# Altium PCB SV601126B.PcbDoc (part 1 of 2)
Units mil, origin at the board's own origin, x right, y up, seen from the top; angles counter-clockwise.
Board outline 2770 x 1865 mil, 4 copper layers (Top Layer, MidLayer1, MidLayer2, Bottom Layer), stack 61.2 mil thick; 102 components, 62 nets, 339 pads, 118 vias.
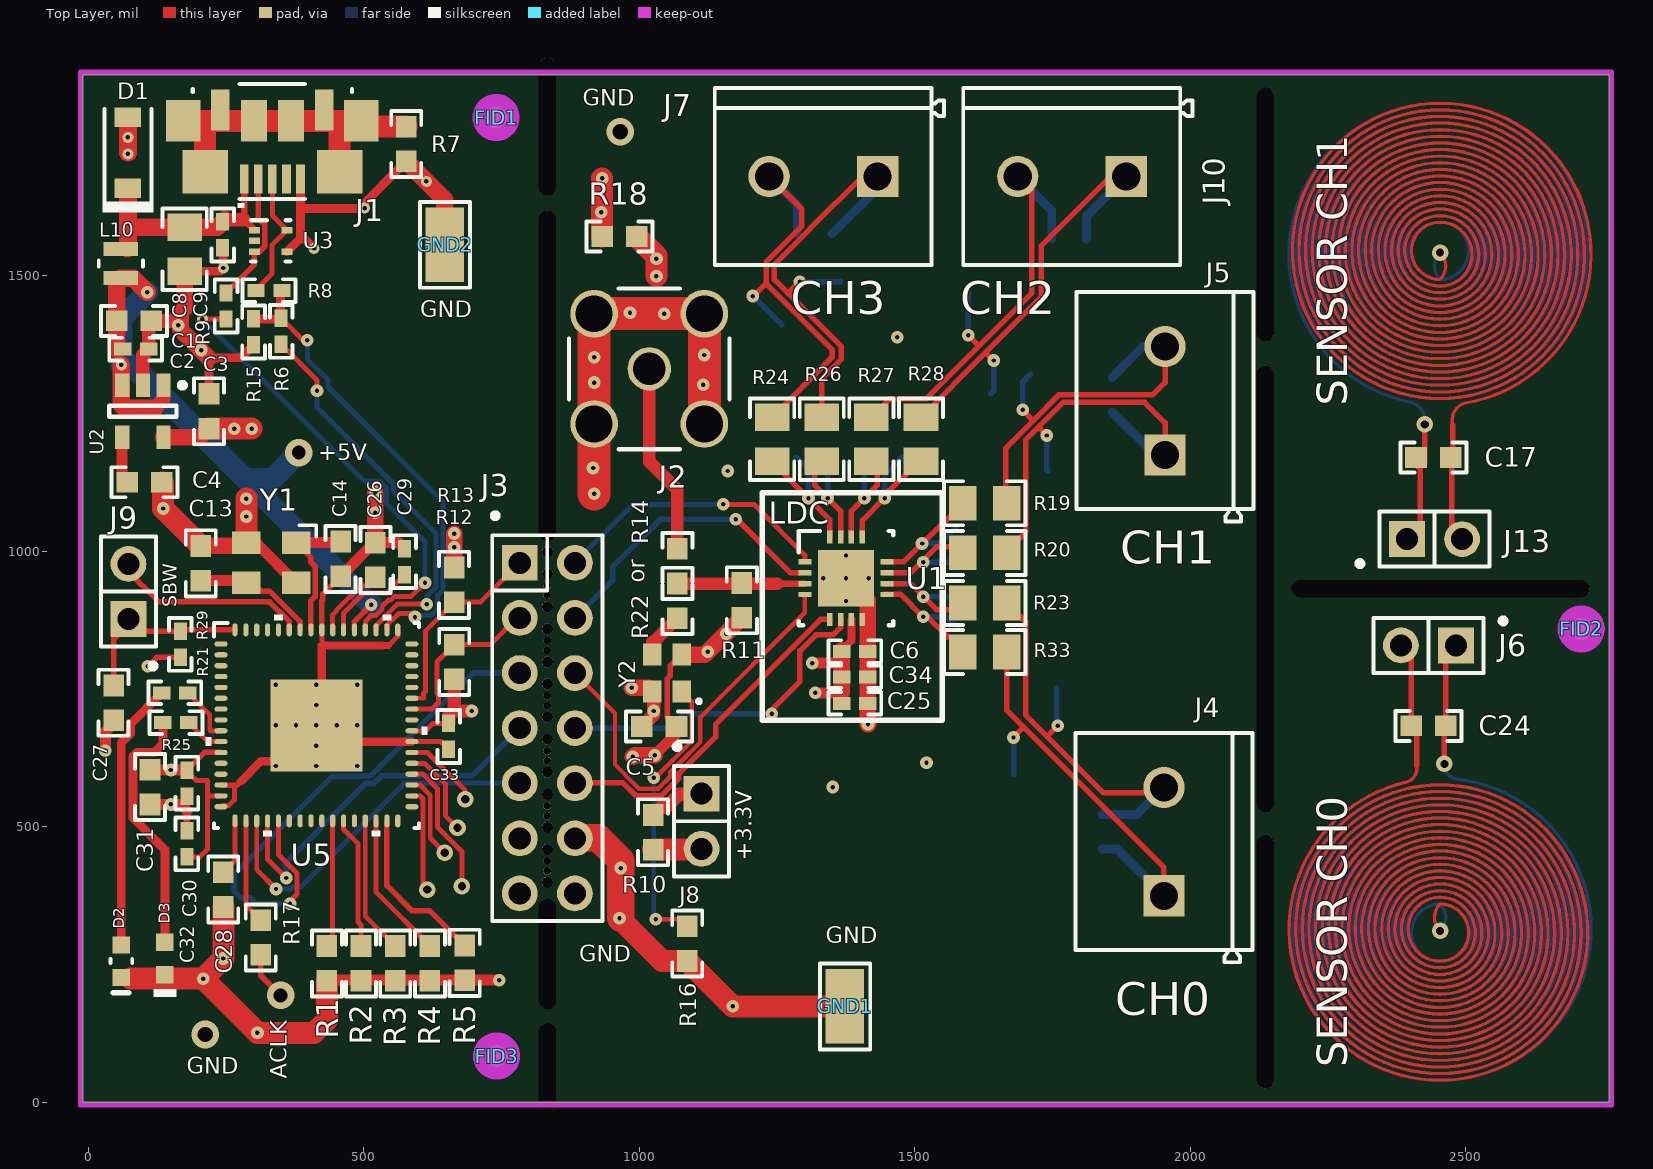
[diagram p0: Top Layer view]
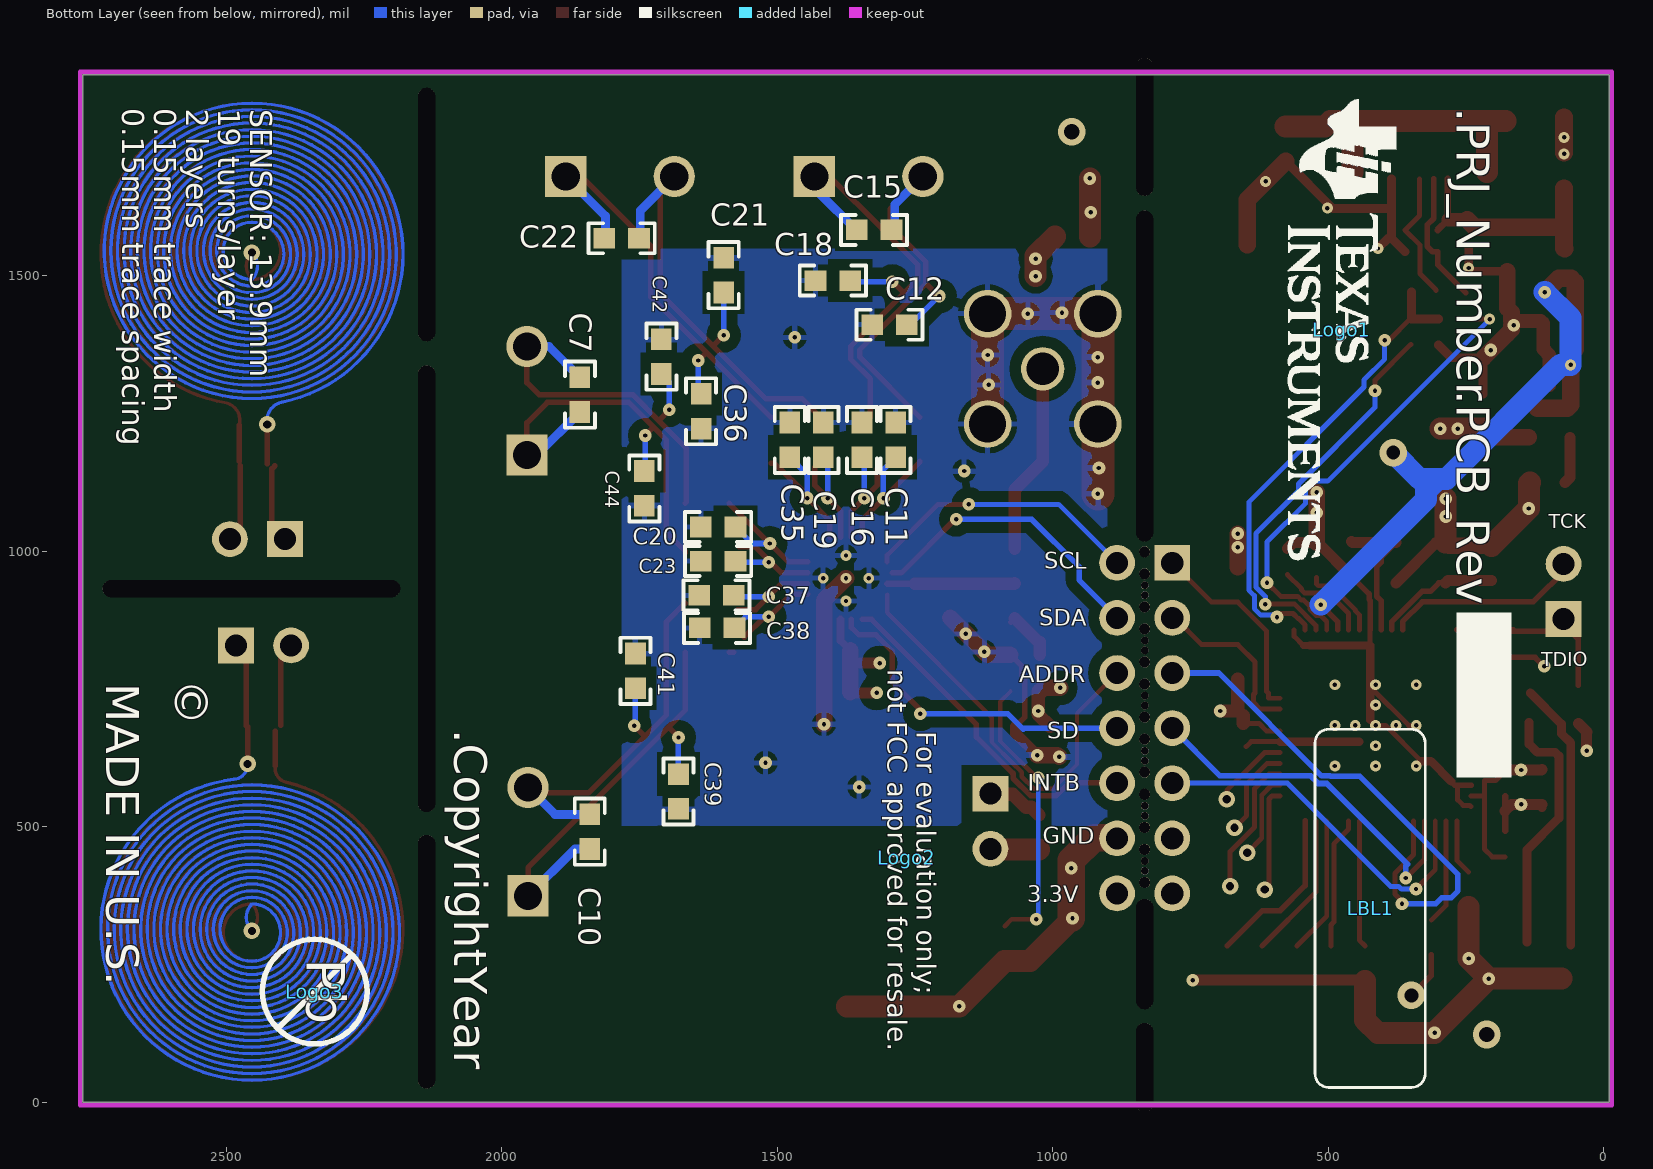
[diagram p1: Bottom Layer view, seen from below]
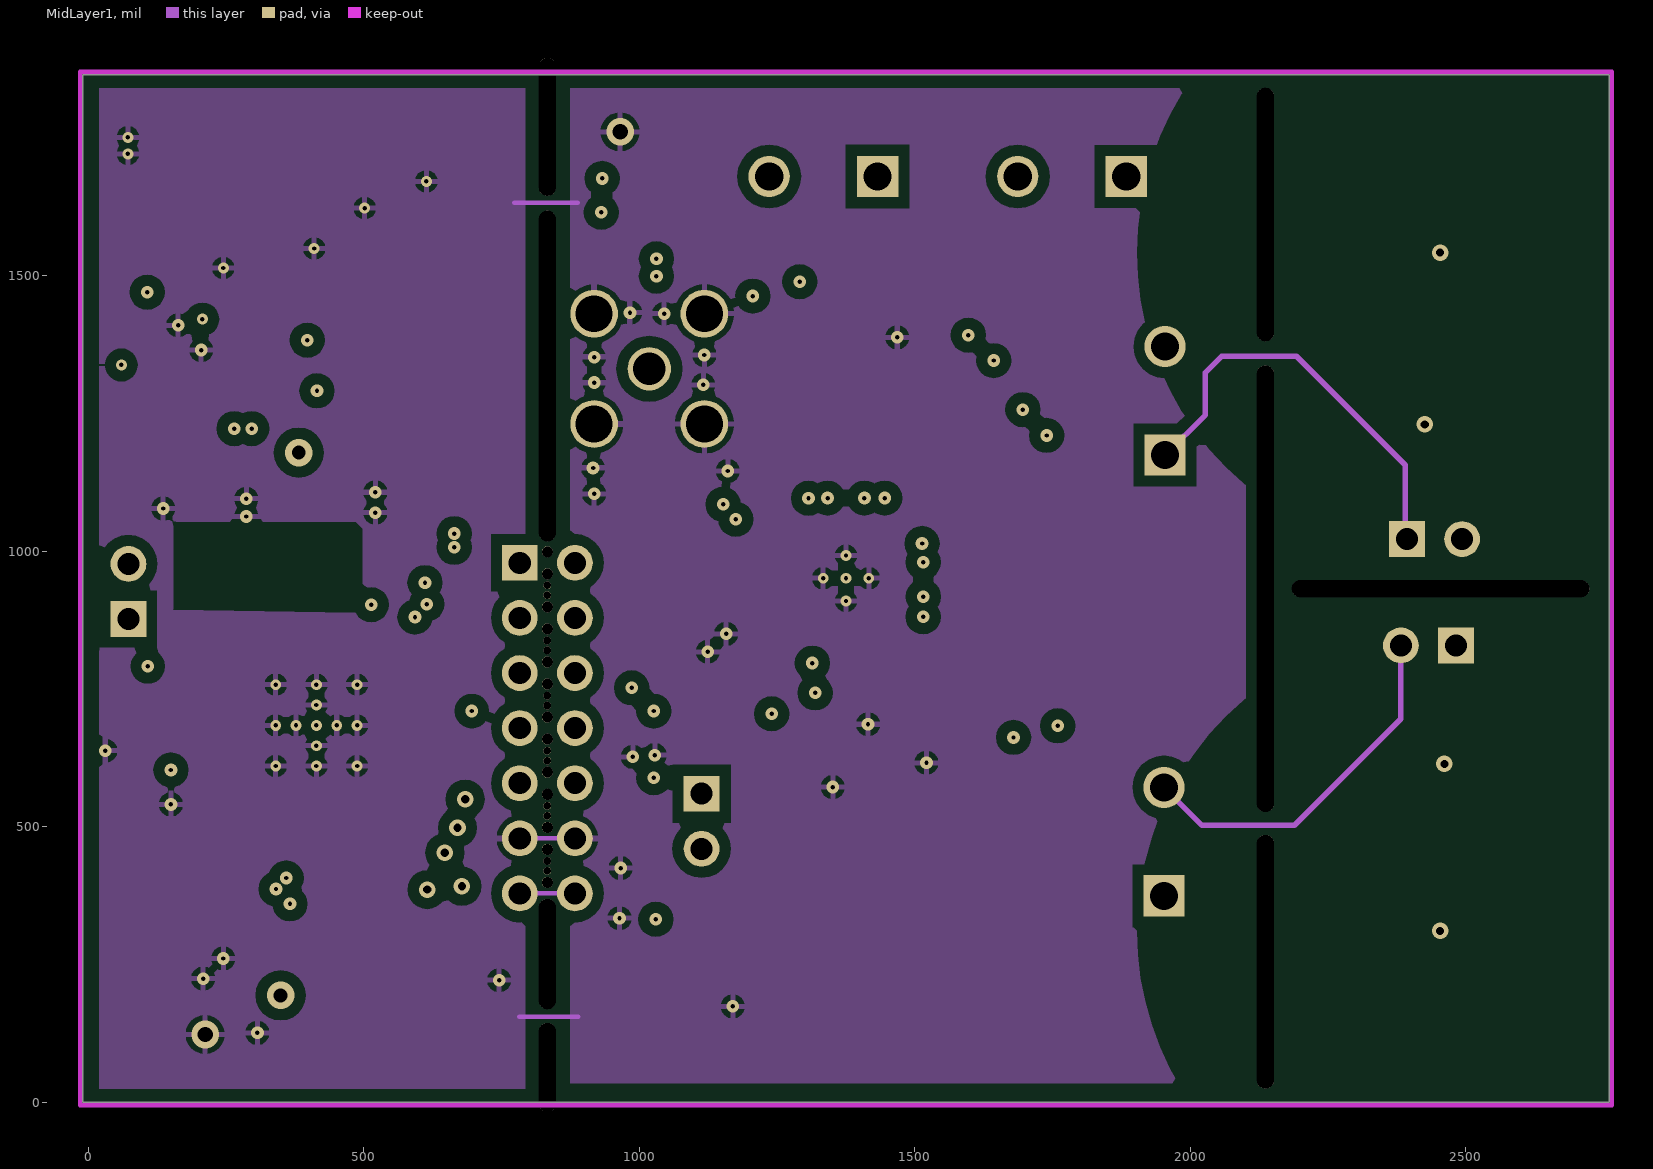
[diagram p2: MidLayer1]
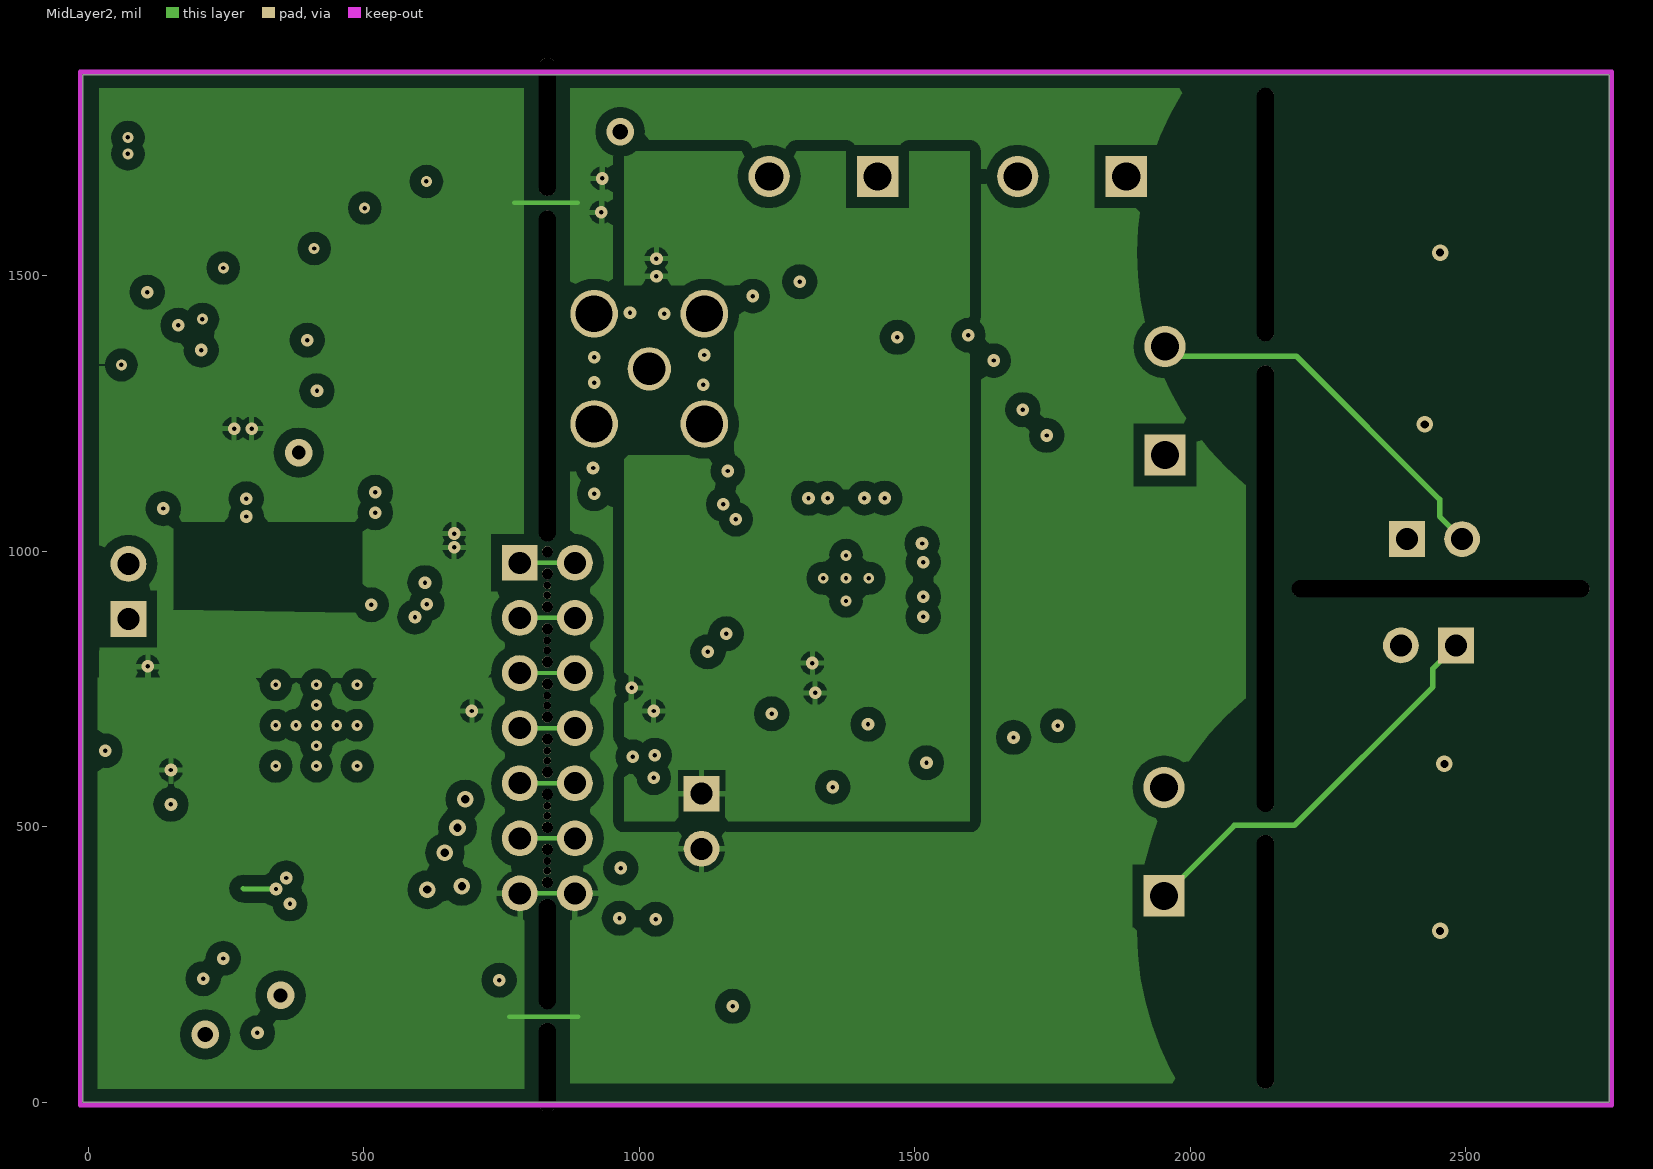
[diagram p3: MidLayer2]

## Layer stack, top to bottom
Top Solder: solder mask 0.4, Solder Resist, Dk 3.5
Top Layer: signal copper 1.4
Dielectric1: core 12.6, FR-4, Dk 3.9
MidLayer1: signal copper 1.4
Dielectric2: prepreg 30.4, FR-4, Dk 3.9
MidLayer2: signal copper 1.4
Dielectric3: core 12.6, FR-4, Dk 4.8
Bottom Layer: signal copper 1.4
Bottom Solder: solder mask 0.4, Solder Resist, Dk 3.5

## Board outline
-10,0 2760,0 2760,1865 -10,1865

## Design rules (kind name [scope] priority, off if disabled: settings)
AcuteAngle [All] p1: minimum=4.50000000000000E+0001 checktracksonly=FALSE
AssemblyTestPointUsage [All] p1: valid=2
Clearance Clearance_BoardEdge_MountingHoles [OnCopper and InComponentClass('Mounting Holes') vs IsKeepOut] p1: gap=40
Clearance Clearance_BoardEdge_Poly [OnCopper and InPoly vs IsKeepOut] p2: gap=25
Clearance Clearance_BoardEdge [OnCopper and Not InComponentClass('Logo') and not InComponentClass('FiducialMark') and not InRegion(1000,500,4000,800) and Not IsKeepout vs IsKeepOut] p3: gap=30
Clearance Clearance_Poly [InPolygon] p4: gap=20
Clearance [All] p5: gap=4
ComponentClearance ComponentClearance_Logo [InComponentClass('Logo')] p1: gap=50 collisioncheckmode=3 verticalgap=10 showdistances=FALSE
ComponentClearance ComponentClearance_ScrewToNut [(HasFootprint('NY PMS 440 0025 PH')) vs (HasFootprint('Keystone_1902C'))] p2: gap=5 collisioncheckmode=3 verticalgap=10 showdistances=FALSE
ComponentClearance ComponentClearance_MountingHoles [InComponentClass('Mounting Holes')] p3: gap=250 collisioncheckmode=3 verticalgap=100000 showdistances=FALSE
ComponentClearance ComponentClearance_SmallPassives [HasFootprint('0201*') or HasFootprint('0402*') or HasFootprint('0508') or HasFootprint('0603*') or HasFootprint('0612') or HasFootprint('0805*') or HasFootprint('0815*') or HasFootprint('0830*') or HasFootprint('1206*') or HasFootprint('1210*') or HasFootprint('1808*') or HasFootprint('1812*') or HasFootprint('1825*') or HasFootprint('2010*') or HasFootprint('2220*') or HasFootprint('2225*') or HasFootprint('2512*') or HasFootprint('2728*') or HasFootprint('3518*') vs HasFootprint('0201*') or HasFootprint('0402*') or HasFootprint('0508') or HasFootprint('0603*') or HasFootprint('0612') or HasFootprint('0805*') or HasFootprint('0815*') or HasFootprint('0830*') or HasFootprint('1206*') or HasFootprint('1210*') or HasFootprint('1808*') or HasFootprint('1812*') or HasFootprint('1825*') or HasFootprint('2010*') or HasFootprint('2220*') or HasFootprint('2225*') or HasFootprint('2512*') or HasFootprint('2728*') or HasFootprint('3518*')] p4: gap=20 collisioncheckmode=3 verticalgap=10 showdistances=FALSE
ComponentClearance ComponentClearance_THtoSMT [IsThruComponent vs IsSMTComponent] p5: gap=75 collisioncheckmode=3 verticalgap=30 showdistances=FALSE
ComponentClearance ComponentClearance_THtoTH [IsThruComponent vs IsThruComponent] p6: gap=78.74 collisioncheckmode=3 verticalgap=30 showdistances=TRUE
ComponentClearance [All] p7: gap=40 collisioncheckmode=3 verticalgap=10 showdistances=FALSE
DiffPairsRouting [All] p1: maxlimit=100 minlimit=10 mostfreqgap=10 toplayer_minwidth=15 toplayer_maxwidth=15 toplayer_prefwidth=15 midlayer1_minwidth=15 midlayer1_maxwidth=15 midlayer1_prefwidth=15 midlayer2_minwidth=15 midlayer2_maxwidth=15 midlayer2_prefwidth=15 bottomlayer_minwidth=15 bottomlayer_maxwidth=15 bottomlayer_prefwidth=15 maxuncoupledlength=1000
FabricationTestPointUsage TestPointUsage [All] p1: valid=2 allowmultiple=FALSE
FabricationTestpoint Testpoint [All] p1: side=3 testpointundercomponent=TRUE minsize=40 maxsize=100 preferedsize=60 minholesize=0 maxholesize=40 preferedholesize=32 testpointgrid=1 allowsidetop=TRUE allowsidebottom=TRUE usegrid=TRUE gridtolerance=0.01
FanoutControl Fanout_LCC [IsLCC] p1: bgadir=Out bgaviamode=Centered fanoutstyle=Auto fanoutdirection=Alternating viagrid=1 // Fanout_LCC (Default Rule)
FanoutControl Fanout_BGA [IsBGA] p2: bgadir=Out bgaviamode=Centered fanoutstyle=Auto fanoutdirection=Alternating viagrid=1 // Fanout_BGA (Default Rule)
FanoutControl Fanout_Default [All] p4: bgadir=Out bgaviamode=Centered fanoutstyle=Auto fanoutdirection=Alternating viagrid=1 // Fanout_Default (Default Rule)
FanoutControl Fanout_Small [(CompPinCount < 5)] p5: bgadir=Out bgaviamode=Centered fanoutstyle=Auto fanoutdirection=OutThenIn viagrid=1 // Fanout_Small (Default Rule)
HoleSize [All] p1: absolutevalues=TRUE maxlimit=251 minlimit=7.87 maxpercent=80.000 minpercent=20.000
HoleToHoleClearance [All] p1: gap=21 allowstackedmicrovias=TRUE
MinimumAnnularRing MinimumAnnularRing_ThermalPadVias [IsVia and InAnyComponent] p1: minimumring=5.91
MinimumAnnularRing [All] p2: minimumring=6
MinimumSolderMaskSliver MinimumSolderMaskSliver_Logo [InComponentClass('Logo') vs InComponentClass('Logo')] p1: minsoldermaskwidth=0.7
MinimumSolderMaskSliver [All] p2: minsoldermaskwidth=3.94
PlaneConnect [All] p1: planeconnectstyle=Relief reliefexpansion=10 reliefentries=4 reliefconductorwidth=10 reliefairgap=10
PolygonConnect [All] p1: connectstyle=Relief reliefconductorwidth=10 reliefentries=4 polygonreliefangle="90 Angle" airgapwidth=10
RoutingVias ThermalPadVias [IsVia and InAnyComponent] p1: holewidth=7.87 width=19.68 viastyle="Through Hole" minholewidth=7.87 minwidth=19.68 maxholewidth=12.99 maxwidth=23.62
RoutingVias [All] p2: holewidth=16 width=34 viastyle="Through Hole" minholewidth=7.87 minwidth=20 maxholewidth=40 maxwidth=65
SMDToCorner [All] p1: distance=30000
SilkToSilkClearance [All] p1: silktosilkclearance=5
SilkToSolderMaskClearance SilkscreenOverComponentPads [IsPad] p1: minsilkscreentomaskgap=5 clearancetoexposedcopper=TRUE
SolderMaskExpansion [All] p1: expansion=1.97
UnpouredPolygon [All] p1: allowunpoured=FALSE
Width [All] p1: maxlimit=100 minlimit=4 preferedwidth=10 checkconnectedcopper=TRUE
14 further rules are at their usual default settings.

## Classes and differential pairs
component class Label: LBL1
component class FiducialMark: FID1 FID2 FID3
component class Logo: Logo1
component class Header: J3 J6 J8 J9 J13

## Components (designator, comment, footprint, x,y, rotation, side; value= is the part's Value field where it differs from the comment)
C1 "C1608X5R1A106M" 0603 83,1418 r0 top
C2 "GRM155R71C104JA88D" 0402 85.99,1366.82 r0 top
C3 "C0603C225K8PACTU" 0603 219,1254 r90 top
C4 "C1608C0G1E103J" 0603 102,1125 r0 top
C5 "C1608C0G1E103J" 0603 1036,682 r0 top
C6 "C1005X7R1C103K" 0402 1391,818 r0 top
C7 "C1608C0G1H331F080AA" 0603 1858,1284 r270 bottom
C8 "C2012X5R1C226K125AC" 0805_HV 175,1548 r270 top
C9 "GRM155R71C104JA88D" 0402 244,1574 r270 top
C10 "C1608C0G1H331F080AA" 0603 1840,491 r270 bottom
C11 "GRM1885C2A180JA01D" 0603 1285,1202 r270 bottom
C12 "GRM1885C2A180JA01D" 0603 1296,1411 r180 bottom
C13 "GRM1885C2A180JA01D" 0603 204,978 r270 top
C14 "GRM1885C2A180JA01D" 0603 458,986 r90 top
C15 "C1608C0G1H331F080AA" 0603 1324,1583 r0 bottom
C16 "GRM1885C2A180JA01D" 0603 1346,1202 r90 bottom
C17 "C1608C0G1H331F080AA" 0603 2441,1170 r0 top
C18 "GRM1885C2A180JA01D" 0603 1399,1491 r0 bottom
C19 "GRM1885C2A180JA01D" 0603 1416,1202 r270 bottom
C20 "GRM1885C2A180JA01D" 0603 1607,1044 r180 bottom
C21 "GRM1885C2A180JA01D" 0603 1597,1501 r270 bottom
C22 "C1608C0G1H331F080AA" 0603 1782,1568 r0 bottom
C23 "GRM1885C2A180JA01D" 0603 1607,982 r0 bottom
C24 "C1608C0G1H331F080AA" 0603 2432,683 r0 top
C25 "GRM155R61A105KE15D" 0402 1391,724 r0 top
C26 "06035A221FAT2A" 0603 521,984 r270 top
C27 "C0603X222K5RACTU" 0603 46,725 r90 top
C28 "C0603C474K8RACTU" 0603 245,386 r270 top
C29 "C1005C0G1H221F050BA" 0402 574,981 r90 top
C30 "GRM155R71C104JA88D" 0402 179,579 r270 top
C31 "C1608X5R1A106M" 0603 112,572 r270 top
C32 "GRM155R71C104JA88D" 0402 179,469 r90 top
C33 "GRM155R71C104JA88D" 0402 654,664 r270 top
C34 "GRM155R71C104JA88D" 0402 1391,772 r0 top
C35 "GRM1885C2A180JA01D" 0603 1477,1202 r90 bottom
C36 "GRM1885C2A180JA01D" 0603 1638,1254 r270 bottom
C37 "GRM1885C2A180JA01D" 0603 1610,920 r180 bottom
C38 "GRM1885C2A180JA01D" 0603 1609,861 r0 bottom
C39 "GRM1885C2A180JA01D" 0603 1679,564 r90 bottom
C41 "GRM1885C2A180JA01D" 0603 1757,783 r90 bottom
C42 "GRM1885C2A180JA01D" 0603 1710,1353 r270 bottom
C44 "GRM1885C2A180JA01D" 0603 1741,1114 r270 bottom
D1 "MMSZ5232B-7-F" SOD-123 72,1723 r90 top
D2 "LG L29K-G2J1-24-Z" "LG L29K_GREEN" 60,256 r270 top
D3 "SML-LX0603SRW-TR" SML-LX0603SRW_SuperRed 139,261 r270 top
FID1 "Fiducial" Fiducial10-20 740,1787 r0 top
FID2 "Fiducial" Fiducial10-20 2709,859 r0 top
FID3 "Fiducial" Fiducial10-20 741,84 r0 top
GND1 "5015" Testpoint_Keystone_Miniature 1373,174 r90 top
GND2 "5015" Testpoint_Keystone_Miniature 647,1556 r90 top
J1 "ZX62R-B-5P" Hirose_ZX62R-B-5P 334,1781 r90 top
J2 "901-144-8RFX" Amphenol_901-144-8RFX 1018,1331 r90 top
J3 "TSW-107-07-G-D" TSW-107-07-G-D 833,679 r270 top
J4 "1729018" Phoenix_1729018 1952,473 r90 top
J5 "1729018" Phoenix_1729018 1954,1273 r90 top
J6 "TSW-102-07-G-S" TSW-102-07-G-S 2432,829 r180 top
J7 "1729018" Phoenix_1729018 1334,1680 r180 top
J8 "TSW-102-07-G-S" TSW-102-07-G-S 1113,510 r270 top
J9 "TSW-102-07-G-S" TSW-102-07-G-S 73,927 r90 top
J10 "1729018" Phoenix_1729018 1785,1680 r180 top
J13 "TSW-102-07-G-S" TSW-102-07-G-S 2443,1022 r0 top
L10 "VLS201610ET-100M" VLS201610ET 59,1522 r270 top
LBL1 "Size: 0.65\" x 0.20 \"" Label_650x200 424,352 r90 bottom
Logo1 "Texas Instruments" TI_Stacked_Overlay_Small 475,1402 r270 bottom
Logo2 "FCC disclaimer" FCC_disclaimer_stacked 1265,444 r270 bottom
Logo3 "Pb-Free Symbol" Pb-Free_Overlay_Medium 2339,201 r270 bottom
R1 "CRCW06030000Z0EA" 0603 433,252 r270 top
R2 "CRCW06030000Z0EA" 0603 495,252 r270 top
R3 "CRCW06030000Z0EA" 0603 557,252 r270 top
R4 "CRCW06030000Z0EA" 0603 620,252 r270 top
R5 "CRCW06030000Z0EA" 0603 683,253 r270 top
R6 "CRCW04021K50JNED" 0402 350,1399 r270 top
R7 "CRCW060333R0JNEA" 0603 577,1739 r90 top
R8 "CRCW040210R0FKED" 0402 328,1473 r0 top
R9 "CRCW040210R0FKED" 0402 250,1445 r270 top
R10 "CRCW06030000Z0EA" 0603 1025,490 r90 top
R11 "CRCW060350R0FKEA" 0603 1186,911 r90 top
R12 "RC0603FR-074K7L" 0603 664,799 r270 top
R13 "RC0603FR-074K7L" 0603 664,939 r90 top
R14 "CRCW060333R0JNEA" 0603 1069,973 r90 top
R15 "RC0402JR-071ML" 0402 300,1398 r90 top
R16 "CRCW06030000Z0EA" 0603 1087,288 r90 top
R17 "CRCW060333R0JNEA" 0603 313,299 r270 top
R18 "CRCW06030000Z0EA" 0603 964,1571 r0 top
R19 "CRCW08050000Z0EA" 0805_HV 1627,1087 r0 top
R20 "CRCW08050000Z0EA" 0805_HV 1627,997 r0 top
R21 "CRCW04021K00JNED" 0402 157,743 r180 top
R22 "CRCW06030000Z0EA" 0603 1069,910 r90 top
R23 "CRCW08050000Z0EA" 0805_HV 1627,906 r0 top
R24 "CRCW08050000Z0EA" 0805_HV 1241,1203 r90 top
R25 "CRCW04021K00JNED" 0402 159,689 r180 top
R26 "CRCW08050000Z0EA" 0805_HV 1331,1203 r90 top
R27 "CRCW08050000Z0EA" 0805_HV 1421,1203 r90 top
R28 "CRCW08050000Z0EA" 0805_HV 1511,1203 r90 top
R29 "CRCW040233K0JNED" 0402 167,831 r90 top
R33 "CRCW08050000Z0EA" 0805_HV 1627,817 r0 top
U1 "LDC1314RGH" RGH0016A 1375,951 r0 top
U2 "LP2985AIM5-3.3/NOPB" MF05A_N 99,1254 r270 top
U3 "TPD2E001DRLR" DRL0005A 331,1563 r0 top
U5 "MSP430F5528IRGC" RGC0064B 414,684 r0 top
Y1 "ABM8-24.000MHZ-B2-T" XTAL_ABM8 332,979 r270 top
Y2 "625L3C040M00000" OSC_CTS_625 1050,779 r180 top

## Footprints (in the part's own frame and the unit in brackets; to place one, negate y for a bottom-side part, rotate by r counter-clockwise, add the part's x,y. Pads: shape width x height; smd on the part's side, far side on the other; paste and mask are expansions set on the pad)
0402 [mm] "0402 from SM-752 data"
  rect 0.8x0.6 smd: 1(-0.6,0) 2(0.6,0)
  silkscreen extent -1.22,-0.52 1.22,0.52, body extent -0.55,-0.3 0.55,0.3, height 0.6
0603 [mm] "0603 from SM-752 data"
  rect 1x0.95 smd: 1(-0.8,0) 2(0.8,0)
  silkscreen extent -1.52,-0.69 1.52,0.69, body extent -0.87,-0.47 0.87,0.47, height 0.85
0805_HV [mil] "0805 with 30mil clearance between pads"
  rect 50x63 smd: 1(-40,0) 2(40,0)
  silkscreen extent -74,-40 74,40, body extent -43,-29 43,29, height 43
Amphenol_901-144-8RFX [mm] "SMA Straight Jack, TH"
  round 2 hole 1.5: 1(0,0)
  round 2.2 hole 1.7: 2(-2.54,2.54) 3(-2.54,-2.54) 4(2.54,-2.54) 5(2.54,2.54)
  silkscreen extent -3.7,-3.7 3.7,3.7, body extent -3.7,-3.7 3.7,3.7, height 9.93
DRL0005A [mm] "SOTFL, 5-Flat Leads, Body 1.2x1.6x0.6mm, Pitch 0.5mm, TI recommended"
  rect 0.5x0.3 smd: 1(-0.75,0.5) 2(-0.75,0) 3(-0.75,-0.5) 4(0.75,-0.5) 5(0.75,0.5)
  silkscreen extent -0.9,-0.95 0.9,0.95, body extent -0.85,-0.85 0.85,0.85, height 0.62
FCC_disclaimer_stacked [mil]
Fiducial10-20 [mm]
  round 1 smd mask+0.5: 1(0,0)
  Top Layer keep-out circle w1.178: c0,0 r0.5
Hirose_ZX62R-B-5P [mm] "Hirose"
  rect 1.35x0.4 smd: 1(-2.68,1.3) 2(-2.68,0.65) 3(-2.68,0) 4(-2.68,-0.65) 5(-2.68,-1.3)
  rect 2x2.1 smd: 6(-2.35,-3.1) 7(-2.35,3.1)
  rect 1.9x1.6 smd: 8(0,-4.1) 13(0,4.1)
  rect 1.88x0.85 smd: 9(0.495,-2.4) 12(0.495,2.4)
  rect 1.9x1.2 smd: 10(0,-0.85) 11(0,0.85)
  silkscreen extent -4,-3.67 1.7,3.67, body extent -2.57,-3.48 2.11,3.45, height 2.65
Label_650x200 [mil] "Thermal Transfer Label"
  round 1 on Mech14: 0(0,0)
  silkscreen extent -325,-100 325,100, body extent -326,-101 326,101, height 1
"LG L29K_GREEN" [mm] "OSRAM"
  rect 0.8x0.8 smd paste-0.4: 1(-0.75,0) 2(0.75,0)
  silkscreen extent -0.1,-0.5 1.45,0.5, body extent -0.9,-0.45 0.9,0.45, height 0.67
MF05A_N [mm] "SOT23, 5-Leads, Body 2.9x1.6mm, Pitch 0.95mm, Lead Span 2.8mm, IPC Medium Density"
  rect 1.1x0.65 smd: 1(-1.2,0.95) 2(-1.2,0) 3(-1.2,-0.95) 4(1.2,-0.95) 5(1.2,0.95)
  silkscreen extent -1.32,-1.55 0.25,1.95, body extent -0.9,-1.55 0.9,1.55, height 1.19
OSC_CTS_625 [mm] "CTS"
  rect 0.85x1 smd: 1(-0.675,0.85) 2(-0.675,-0.85) 3(0.675,-0.85) 4(0.675,0.85)
  silkscreen extent -1.53,1.25 -1.43,1.35, body extent -1.1,-1.35 1.1,1.35, height 1.02
Pb-Free_Overlay_Medium [mil]
  silkscreen extent -95,-95 95,95
Phoenix_1729018 [mm] "Phoenix Contact"
  rect 1.905x1.905 hole 1.3: 1(-2.5,0)
  round 1.9 hole 1.3: 2(2.5,0)
  silkscreen extent -5.56,-4.08 5.01,4.07, body extent -5.56,-4.08 5.01,4.07, height 10
RGC0064B [mm]
  oval 0.6x0.24 smd mask+0.07: 1(-4.4,3.75) 2(-4.4,3.25) 3(-4.4,2.75) 4(-4.4,2.25) 5(-4.4,1.75) 6(-4.4,1.25) 7(-4.4,0.75) 8(-4.4,0.25) 9(-4.4,-0.25) 10(-4.4,-0.75) 11(-4.4,-1.25) 12(-4.4,-1.75) 13(-4.4,-2.25) 14(-4.4,-2.75) 15(-4.4,-3.25) 16(-4.4,-3.75) 33(4.4,-3.75) 34(4.4,-3.25) 35(4.4,-2.75) 36(4.4,-2.25) 37(4.4,-1.75) 38(4.4,-1.25) 39(4.4,-0.75) 40(4.4,-0.25) 41(4.4,0.25) 42(4.4,0.75) 43(4.4,1.25) 44(4.4,1.75) 45(4.4,2.25) 46(4.4,2.75) 47(4.4,3.25) 48(4.4,3.75)
  oval 0.24x0.6 smd mask+0.07: 17(-3.751,-4.4) 18(-3.251,-4.4) 19(-2.751,-4.4) 20(-2.251,-4.4) 21(-1.75,-4.4) 22(-1.25,-4.4) 23(-0.75,-4.4) 24(-0.25,-4.4) 25(0.25,-4.4) 26(0.75,-4.4) 27(1.25,-4.4) 28(1.75,-4.4) 29(2.251,-4.4) 30(2.751,-4.4) 31(3.251,-4.4) 32(3.751,-4.4) 49(3.751,4.4) 50(3.251,4.4) 51(2.751,4.4) 52(2.251,4.4) 53(1.75,4.4) 54(1.25,4.4) 55(0.75,4.4) 56(0.25,4.4) 57(-0.25,4.4) 58(-0.75,4.4) 59(-1.25,4.4) 60(-1.75,4.4) 61(-2.251,4.4) 62(-2.751,4.4) 63(-3.251,4.4) 64(-3.751,4.4)
  rect 4.25x4.25 smd paste-2.112: 65(0,0)
  silkscreen extent -5.1,-5.1 5.1,5.1, body extent -4.57,-4.57 4.57,4.57, height 1.01
RGH0016A [mm] "QFN, 16-Leads, Body 4x4mm, Pitch 0.5mm, TI Recommended"
  rect 0.6x0.25 smd: 1(-1.9,0.75) 2(-1.9,0.25) 3(-1.9,-0.25) 4(-1.9,-0.75) 9(1.9,-0.75) 10(1.9,-0.25) 11(1.9,0.25) 12(1.9,0.75)
  rect 0.25x0.6 smd: 5(-0.75,-1.9) 6(-0.25,-1.9) 7(0.25,-1.9) 8(0.75,-1.9) 13(0.75,1.9) 14(0.25,1.9) 15(-0.25,1.9) 16(-0.75,1.9)
  rect 2.6x2.6 smd paste-1.3: 17(0,0)
  silkscreen extent -2.17,-2.17 2.17,2.17, body extent -2.05,-2.05 2.05,2.05, height 0.81
SML-LX0603SRW_SuperRed [mm] "Lumex Opto/Components Inc"
  rect 0.8x0.8 smd: 1(-0.75,0) 2(0.75,0)
  silkscreen extent 1.4,-0.53 1.78,0.52, body extent -0.92,-0.53 0.92,0.53, height 1.1
SOD-123 [mm] "On Semi recommended land pattern"
  rect 0.915x1.22 smd: 1(-1.637,0) 2(1.637,0)
  silkscreen extent -2.74,-1.17 2.03,1.17, body extent -1.93,-0.9 1.93,0.9, height 1.35
Testpoint_Keystone_Miniature [mil] "Miniature SMT test point"
  rect 135x70 smd: 1(0,0)
  silkscreen extent -78,-46 78,45, body extent -52,-20 52,20, height 61
TI_Stacked_Overlay_Small [mil]
  silkscreen extent -418,-98 418,98
TSW-102-07-G-S [mm] "Samtec 100mil, 1x2, 230 mil above insulator"
  rect 1.65x1.65 hole 1.016 mask+0: 1(-1.27,0)
  round 1.65 hole 1.016 mask+0: 2(1.27,0)
  silkscreen extent -3.57,-1.27 2.54,1.27, body extent -2.54,-1.27 2.54,1.27, height 8.38
TSW-107-07-G-D [mm] "Samtec 100mil, 2x7, 230 mil above insulator"
  rect 1.65x1.65 hole 1.016 mask+0: 1(-7.62,-1.27)
  round 1.65 hole 1.016 mask+0: 2(-7.62,1.27) 3(-5.08,-1.27) 4(-5.08,1.27) 5(-2.54,-1.27) 6(-2.54,1.27) 7(0,-1.27) 8(0,1.27) 9(2.54,-1.27) 10(2.54,1.27) 11(5.08,-1.27) 12(5.08,1.27) 13(7.62,-1.27) 14(7.62,1.27)
  silkscreen extent -9.91,-2.54 8.89,2.54, body extent -8.89,-2.54 8.89,2.54, height 8.38
VLS201610ET [mm] "TDK"
  rect 0.65x1.6 smd: 1(-0.675,0) 2(0.675,0)
  silkscreen extent -0.15,-1.02 0.15,1.02, body extent -1.05,-0.85 1.05,0.85, height 0.95
XTAL_ABM8 [mm] "Abracon recommended land pattern"
  rect 1.05x1.3 smd: 1(-0.925,1.15) 2(-0.925,-1.15) 3(0.925,-1.15) 4(0.925,1.15)
  silkscreen extent -1.73,1.3 -1.2,2.07, body extent -1.35,-1.7 1.35,1.7, height 0.8

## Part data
C1 C31: "CAP, CERM, 10uF, 10V, +/-20%, X5R, 0603"
C2 C9 C30 C32 C33 C34: library part 0402YC132KAT2A, "CAP CER 0.1UF 16V 5% X7R 0402"
C3: "CAP, CERM, 2.2uF, 10V, +/-10%, X5R, 0603"
C4 C5: "CAP, CERM, 0.01uF, 25V, +/-5%, C0G/NP0, 0603"
C6: "CAP, CERM, 0.01 µF, 16 V, +/- 10%, X7R, 0402"
C7 C10 C15 C17 C22 C24: "CAP, CERM, 330pF, 50V, +/-1%, C0G/NP0, 0603"
C8: "CAP, CERM, 22uF, 16V, +/-10%, X5R, 0805"
C11 C12 C13 C14 C16 C18 C19 C20 C21 C23 C35 C36 C37 C38 C39 C41 C42 C44: "CAP, CERM, 18pF, 100V, +/-5%, C0G/NP0, 0603"
C25: "CAP, CERM, 1uF, 10V, +/-10%, X5R, 0402"
C26: "CAP, CERM, 220pF, 50V, +/-1%, C0G/NP0, 0603"
C27: "CAP, CERM, 2200pF, 50V, +/-10%, X7R, 0603"
C28: "CAP, CERM, 0.47uF, 10V, +/-10%, X7R, 0603"
C29: library part 0402YC132KAT2A, "CAP CER 220PF 50V 1% NP0 0402"
D1: "Diode, Zener, 5.6V, 500mW, SOD-123"
D2: "LED, Green, SMD"
D3: "LED, Super Red, SMD"
FID1 FID2 FID3: "Fiducial mark.  There is nothing to buy or mount."
GND1 GND2: "Test Point, Miniature, SMT"
J1: "Connector, Receptacle, Micro-USB Type B, SMT"
J2: "SMA Straight Jack, Gold, 50 Ohm, TH"
J3: "Header, 100mil, 7x2, Gold, TH"
J4 J5 J7 J10: "TERM BLOCK 2POS 5mm, TH"
J6 J8 J9 J13: "Header, TH, 100mil, 2x1, Gold plated, 230 mil above insulator"
L10: "Inductor, Shielded, Ferrite, 10 µH, 0.4 A, 1.38 ohm, SMD"
LBL1: library part THT-14-423-10, "Thermal Transfer Printable Labels, 0.650\" W x 0.200\" H - 10,000 per roll"
Logo1: library part TI_Logo, "Texas Instrument Corporate Signature"
Logo2: library part FCC_disclaimer, "FCC_disclaimer"
Logo3: library part Pb-Free
R1 R2 R3 R4 R5 R10 R16 R18 R22: "RES, 0 ohm, 5%, 0.1W, 0603"
R6: library part CRCW040233K0JNED, "RES 1.5K OHM 1/16W 5% 0402 SMD"
R7 R17: "RES, 33 ohm, 5%, 0.1W, 0603"
R8 R9: "RES, 10.0, 1%, 0.063 W, 0402"
R11: "RES, 50, 1%, 0.1 W, 0603"
R12 R13: "RES, 4.70k ohm, 1%, 0.1W, 0603"
R14: library part CRCW06030000Z0EA, "RES, 0 ohm, 5%, 0.1W, 0603"
R15: library part CRCW040233K0JNED, "RES,1M ohm, 5%, 0.063W, 0402"
R19 R20 R23 R24 R26 R27 R28 R33: "RES, 0 ohm, 5%, 0.125W, 0805"
R21 R25: "RES, 1.0k ohm, 5%, 0.063W, 0402"
R29: "RES, 33k ohm, 5%, 0.063W, 0402"
U1: "Multi-Channel 12/28-Bit Inductance to Digital Converter with I2C, RGH0016A"
U2: "Micropower 150 mA Low-Noise Ultra Low-Dropout Regulator, 5-pin SOT-23, Pb-Free"
U3: "Low-Capacitance + / - 15 kV ESD-Protection Array for High-Speed Data Interfaces, 2 Channels, -40 to +85 degC, 5-pin SOT (DRL), Green (RoHS & no Sb/Br)"
U5: "Mixed Signal MicroController, RGC0064B"
Y1: "Crystal, 24.000MHz, 18pF, SMD"
Y2: "OSC, 40 MHz, 3.3 V, SMD"

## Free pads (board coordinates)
  oval 31x162 hole 31 slot 162 at 90 deg unplated: 0(833,63)
  oval 31x200 hole 31 slot 200 at 90 deg unplated: 0(833,269)
  round 20 hole 20 unplated: 0(833,399) 0(833,459) 0(833,499) 0(833,559) 0(833,599) 0(833,659) 0(833,699) 0(833,759) 0(833,799) 0(833,859) 0(833,899) 0(833,959) 0(833,999)
  round 14 hole 14 unplated: 0(833,420) 0(833,438) 0(833,520) 0(833,538) 0(833,620) 0(833,638) 0(833,720) 0(833,738) 0(833,820) 0(833,838) 0(833,920) 0(833,938)
  oval 31x600 hole 31 slot 600 at 90 deg unplated: 0(833,1318)
  oval 31x250 hole 31 slot 250 at 90 deg unplated: 0(833,1770)
  oval 31x460 hole 31 slot 460 at 90 deg unplated: 0(2136,255) 0(2136,1611)
  oval 31x810 hole 31 slot 810 at 90 deg unplated: 0(2136,932)
  oval 540x31 hole 31 slot 540 at 0 deg unplated: 0(2454,932)

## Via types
v1: diameter 23, hole 8, Top Layer to Bottom Layer, tented both sides, 79 vias
v2: diameter 19.68, hole 7.87, Top Layer to Bottom Layer, 18 vias
v3: diameter 20, hole 8, Top Layer to Bottom Layer, tented both sides, 8 vias
v4: diameter 30, hole 15, Top Layer to Bottom Layer, 5 vias
v5: diameter 30, hole 15, Top Layer to Bottom Layer, tented both sides, 4 vias
v6: diameter 50, hole 25, Top Layer to Bottom Layer, 2 vias
v7: diameter 50, hole 28, Top Layer to Bottom Layer, 2 vias

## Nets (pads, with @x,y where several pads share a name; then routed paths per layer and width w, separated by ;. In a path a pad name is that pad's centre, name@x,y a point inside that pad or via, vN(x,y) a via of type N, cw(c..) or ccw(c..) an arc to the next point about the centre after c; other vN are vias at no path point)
+3.3V: C3.1 C30.1 C31.1 C32.1 C33.1 J3.13 J3.14 J8.2 R10.1 R12.2 R13.2 R18.1 R29.1 U2.5 U5.11 U5.15 U5.40 | length 1512.9
  Top Layer w9: C30.1@178.19,601.81 196.46,583.54 216.46,583.54 216.46,459.46 202.38,445.38 C32.1@179,445.38 ; 218.51,556.05 U5.15@240.77,556.05 ; U5.40@587.23,674.16 612.16,674.16 625.62,687.62 C33.1@654,687.62 ; C33.1@649,682 649,692.62 C33.1@654,697.62
  Top Layer w10: v1(108,791) 124.38,807.38 R29.1@167,807.38 ; C30.1@179,602.62 211.17,634.79 U5.11@240.77,634.79 ; C33.1@654,701.57 657.59,705.16
  Top Layer w20: C31.1@112,603.5 112.87,602.62 C30.1@177.38,602.62
  Top Layer w24: C33.1@654,687.62 654,697.62 C33.1@654,701.57 ; R12.2@664,767.5 664,710 v1(696,710)
  Top Layer w30: U2.5@136.4,1206.76 203.25,1206.76 C3.1@219,1222.5 ; R13.2@664,970.5 v1(664,1032)
  Top Layer w40: C3.1@219,1222.5 v1(296.5,1222.5) ; R18.1@932.5,1571 v1(932.5,1676.5) ; R10.1@1025,458.5 1111.5,458.5 J8.2@1113,460
  MidLayer1 w8: J3.13@793,379 J3.14@893,379
  MidLayer2 w8: 764,155 889,155 ; J3.13@773,379 J3.14@883,379 ; 773,1632 888,1632
  other v1: 150,603 664,1007 264.73,1222.5 931,1615
+5V: C1.1 C2.1 L10.2 U2.1 U2.3 U5.53 | length 1291.6
  Top Layer w10: U5.53@482.91,857.23 482.91,872.43 v1(513.49,903)
  Top Layer w26: 120.08,1259.59 136.4,1275.91 136.4,1276.59
  Top Layer w32: C2.1@51.5,1366.82 C1.1@51.5,1418 L10.2@51.5,1487.93 ; L10.2@59,1495.43 81.57,1495.43 v1(107,1470) ; v3(60,1338) 60,1265.8 66.2,1259.59 120.08,1259.59
  Bottom Layer w40: v1(107,1470) 60,1423 v3(60,1338) 78.49,1338 285.71,1130.78 301.43,1130.78 ; v6(382,1179) 333.78,1130.78 301.43,1130.78 ; v1(513.49,903) 322.22,1094.26 322.22,1109.98 301.43,1130.78
ADDR: J3.5 J3.6 U1.4 U5.21 | length 1843.9
  Top Layer w8: J3.6@883,779 955.81,706.19 955.81,613 975,593.81 975,593.18 998.86,569.32 1034.48,569.32 1056.08,590.92 1056.08,599.08 1058.52,601.52 1058.52,601.59 1071.41,614.48 1071.48,614.48 1110.89,653.89 1110.89,698.88 1300.2,888.19 U1.4@1300.2,921.47
  Top Layer w9: U5.21@345.09,510.77 345.09,449.2 379,415.28 379,377.99 v1@361.01,360
  Top Layer w10: v1@361.01,360 v1(366,360)
  MidLayer2 w8: J3.5@783,779 J3.6@883,779
  Bottom Layer w10: v1(366,360) 305,360 293.5,371.5 276.51,371.5 264.5,383.51 264.5,413.49 442.35,591.34 495.62,591.34 496.79,592.5 512,592.5 698.5,779 J3.5@783,779
CLKIN: R11.2 R14.1 R22.2 U1.3 | length 231.3
  Top Layer w12: 1250,941 1250.16,941.16 U1.3@1300.2,941.16
  Top Layer w23: R22.2@1069,941.5 1186,941.18 1250,941
GND: C1.2 C2.2 C3.2 C4.2 C5.2 C6.2 C8.2 C9.2 C11.1 C12.1 C13.1 C14.1 C16.2 C18.2 C19.1 C20.1 C21.1 C23.2 C25.2 C26.1 C27.1 C28.2 C29.2 C30.2 C31.2 C32.2 C33.2 C34.2 C35.2 C36.2 C37.1 C38.2 C39.1 C41.2 C42.1 C44.2 D1.2 D2.2 D3.2 GND1.1 GND2.1 J1.5 J2.2 J2.3 J2.4 J2.5 J3.11 J3.12 R1.2 R2.2 R3.2 R4.2 R5.2 R7.1 R11.1 R15.1 R16.1 U1.8 U1.17 U2.2 U3.4 U5.14 U5.16 U5.39 U5.49 U5.56 U5.65 Y1.2 Y1.4 Y2.2 | length 6578.2
  Top Layer w9: U5.16@240.77,536.36 243.23,538.82 254.99,538.82 265.08,548.91 265.08,570.23 ; U5.65@331,619 396,684 v2(414,684) ; v2(340.18,684) 354,684 U5.65@420.91,750.91 ; 423.85,829 U5.56@423.85,857.23 ; 545.2,829 561.67,845.47 U5.49@561.67,857.23 ; U5.39@587.23,654.47 639.91,654.47 C33.2@649,645.38
  Top Layer w10: U5.14@240.77,575.73 270.59,575.73 276.93,582.07 ; U5.56@423.85,857.23 423.85,910.37 425.87,912.39 425.87,922.37 C14.1@458,954.5 ; C5.2@1067.5,682 1050.84,698.65 1050.84,768.95 1056.11,774.22 1056.11,792 Y2.2@1076.57,812.46
  Top Layer w12: C32.2@178.89,492.62 C32.2@179,492.62 179,529 C30.2@179,555.38 ; 533.45,829 545.2,829
  Top Layer w15: 276.93,582.07 313.86,619 U5.65@331,619 ; U5.65@423.85,693.84 423.85,829 533.45,829 ; U5.65@443.53,654.47 U5.39@587.23,654.47
  Top Layer w16: C31.2@112,535.18 C31.2@112,540.5 ; 175,1394 175,1394.12 ; C8.2@175,1508 239,1508 v3(245,1514) C9.2@245,1549.38 ; 218,1351 276.62,1351 R15.1@300,1374.38 ; C3.2@219,1285.5 219,1350 ; U3.4@360.53,1543.32 385.18,1567.97 ; J1.5@385.18,1675.49 385.18,1622 ; v3(410.01,1549.25) 391.29,1567.97 385.18,1567.97 ; R7.1@577,1707.5 491.5,1622 385.18,1622 ; 385.18,1567.97 385.18,1622
  Top Layer w20: v1(31,638) 31,671.4 30.7,671.7 C27.1@46,687 ; C31.2@112,540.5 167.5,540.5 179,529 ; Y1.2@286.72,1015.42 304.44,1015.42 Y1.4@377.28,942.58 ; R1.2@433,220.5 434,221.5 R5.2@683,221.5 v1(745.5,221.5) ; C14.1@458,954.5 518.99,1015.5 C26.1@521,1015.5 563.13,1015.5 C29.2@574,1004.62 ; v1(1028,630) 1067.5,669.5 C5.2@1067.5,682
  Top Layer w25: U2.2@99,1301.24 99,1356.21 C2.2@109.61,1366.82 109.61,1413.11 C1.2@114.5,1418 151.12,1418
  Top Layer w30: v1@167.38,1410 167.38,1401.74 175,1394.12 ; v1@167.38,1418 167.38,1433.39 175,1441.01 C8.2@175,1508 ; 175,1394 218,1351 219,1350 ; C13.1@204,1009.5 280.8,1009.5 Y1.2@286.72,1015.42 ; C26.1@521,1015.5 v1(521,1107) ; v1(988.31,626.78) 991.53,630 v1(1028,630) ; Y2.2@1076.57,812.46 1118.96,812.46 R11.1@1186,879.5 ; v2(1375,951) 1414.62,911.38 C34.2@1414.62,772 C25.2@1414.62,724 1414.62,686.38 v1(1415,686)
  Top Layer w32: v3@72,1723.01 D1.2@72,1787.47 ; R7.1@577,1707.5 647,1637.5 GND2.1@647,1556
  Top Layer w40: 77,224.47 v1(208.47,224.47) ; C4.2@133.5,1125 135.99,1122.5 v1(135.99,1077.5) C13.1@204,1009.5 ; C28.2@245,354.5 v1(245,261) v1(208.47,224.47) ; Y1.2@286.72,1015.42 v1(286.72,1095.28) ; R1.2@433,220.5 433,149 410,126 v1(306.94,126) v1(208.47,224.47) ; v1(964,334) 1041.5,256.5 R16.1@1087,256.5 v1(1169.5,174) GND1.1@1373,174
  Top Layer w50: J3.12@883,479 884,480 925,480 966,439 v1(966,425) v1@966,334
  Top Layer w60: v1(918,1104) J2.2@918,1231 J2.5@918,1431 J2.4@1118,1431 v1(1118,1356) J2.3@1118,1231
  MidLayer1 w8: 773,1632 888,1632 ; 782,155 889,155 ; J3.11@793,479 J3.12@883,479 J3.12@893,479
  MidLayer2 w8: J3.11@773,479 J3.11@783,479 J3.12@883,479
  other v1: 150,540.5 1351,572 1521,616 1124,817.5 1157.46,849.98 286.72,1063 521,1070 1160.5,1145.5 916,1151 1116,1302 918,1306 918,1352 205,1365 1468,1388 163,1410 1045,1431 983,1433
  other v2: 340.18,610.18 414,610.18 487.82,610.18 414,647.09 377.09,684 450.91,684 487.82,684 414,720.91 340.18,757.82 414,757.82 487.82,757.82 1375,909.66 1333.66,951 1416.34,951 1375,992.34
  other v3: 501.61,1622.67 613.5,1671 72,1721 72,1751
  other v7: 212,123 965,1761
IN0A: C38.1 R33.1 U1.9 | length 226.6
  Top Layer w10: U1.9@1444.8,921.47 1474.53,921.47 v1(1515,881) 1523,881 1559.88,844.12 ; R33.1@1579,817 R33.1@1587,817
  Bottom Layer w10: v1(1515,881) 1555.86,881 1556.68,881.82 C38.1@1577.5,861
IN0B: C37.2 R23.1 U1.10 | length 209.8
  Top Layer w10: U1.10@1444.8,941.16 1491.84,941.16 v1(1515.42,917.58) 1539,894 R23.1@1571,894
  Bottom Layer w10: v1(1515.42,917.58) 1576.08,917.58 C37.2@1578.5,920
IN1A: C23.1 R20.1 U1.11 | length 205.1
  Top Layer w10: U1.11@1444.8,960.84 1491.84,960.84 1539,1008 R20.1@1569,1008
  Bottom Layer w10: v1(1515,980) 1573.5,980 C23.1@1575.5,982
IN1B: C20.2 R19.1 U1.12 | length 261.2
  Top Layer w10: U1.12@1444.8,980.53 1464.61,980.53 1479.53,980.53 v1(1513,1014) 1514,1014 R19.1@1587,1087
  Bottom Layer w10: v1(1513,1014) 1545.5,1014 C20.2@1575.5,1044
IN2A: C35.1 R28.1 U1.13 | length 269.3
  Top Layer w10: U1.13@1404.53,1025.8 1404.53,1055.76 v1(1445.19,1096.42) 1445.19,1102.13 1505.94,1159.84 1510.92,1159.72 R28.1@1511,1159.71
  Bottom Layer w10: v1(1445.19,1096.42) 1445.19,1138.7 C35.1@1477,1170.5
IN2B: C19.2 R27.1 U1.14 | length 223
  Top Layer w10: U1.14@1384.84,1025.8 1384.84,1072.84 v1(1408.42,1096.42) 1432,1120 R27.1@1432,1152
  Bottom Layer w10: v1(1408.42,1096.42) 1408.42,1162.93 C19.2@1416,1170.5
IN3A: C16.1 R26.1 U1.15 | length 219.6
  Top Layer w10: R26.1@1318,1150 1318,1120 1365.16,1072.84 U1.15@1365.16,1025.8
  Bottom Layer w10: v1(1341.58,1096.42) 1341.58,1166.08 C16.1@1346,1170.5
IN3B: C11.2 R24.1 U1.16 | length 264.1
  Top Layer w10: R24.1@1241,1163 1241,1162 v1(1307,1096) 1345.47,1057.53 U1.16@1345.47,1025.8
  Bottom Layer w10: C11.2@1285,1170.5 1307,1148.5 v1(1307,1096)
INTB: J3.9 J3.10 U1.5 U5.19 | length 1438.7
  Top Layer w9: U5.19@305.71,510.77 305.71,422.01 v1(340.72,387)
  Top Layer w10: J3.10@883,579 883,580.18 969.62,580.18 993.47,556.32 1039.87,556.32 1071.52,587.98 1071.52,596.21 1076.79,601.48 1076.87,601.48 1138.26,662.88 1138.26,685.88 1328.58,876.2 U1.5@1345.47,876.2
  MidLayer2 w8: J3.9@783,579 J3.10@873,579
  MidLayer2 w9: 281,388 282,387 v1(340.72,387)
  Bottom Layer w9: v1(340.72,387) 345.72,392 350.72,387 367.28,387 372.28,392 386.95,392 573.95,579 J3.9@783,579
JTAG_RST: C27.2 J9.1 R29.2 U5.64 | length 404.6
  Top Layer w10: C27.2@46,756.5 46,840 ; U5.64@266.33,857.23 164.39,857.23 R29.2@167,854.62 J9.1@95.38,854.62 ; 46,840 71,865 81.38,854.62 J9.1@95.38,854.62 ; 46,840 46,850 J9.1@73,877 J9.1@95.38,854.62
JTAG_TCK: U5.63
JTAG_TDI: U5.61
JTAG_TDO: U5.60
JTAG_TEST: J9.2 U5.59 | length 352.9
  Top Layer w10: J9.2@67,969 128,908 329.09,908 364.78,872.32 U5.59@364.78,857.23
JTAG_TMS: U5.62
MSP_DM: R9.2 U5.52 | length 861.3
  Top Layer w9: v3(207,1421) 249.62,1421 R9.2@250,1421.38 ; U5.52@502.61,857.23 502.61,872.43 513.18,883 521.77,883 533.49,894.72 533.49,900.49 544.32,911.32 548.61,911.32 555.29,918 586,918 v1(611,943)
  Bottom Layer w9: v3(207,1421) 501,1127 529.28,1127 541,1115.28 541,1087 611,1017 v1(611,943)
MSP_DP: R6.1 R8.2 R15.2 U5.50 | length 873.8
  Top Layer w9: R6.1@350,1422.62 389.7,1382.92 v1(397.42,1382.92) ; U5.50@541.98,857.23 541.98,866.45 553.08,877.54 554.54,877.54 564,887 586.37,887 v1(592.84,880.53)
  Top Layer w16: R15.2@300,1421.62 349,1421.62 R8.2@349,1470.38
  Bottom Layer w9: v1(397.42,1382.92) 397.42,1348.58 435,1311 435,1297.93 644,1088.93 644,929.33 634,919.33 634,895.72 622.28,884 596.3,884 v1(592.84,880.53)
MSP_PUR: R6.2 U5.51 | length 710.5
  Top Layer w9: R6.2@350,1375.38 415,1310.38 v1(415,1291) ; U5.51@522.3,857.23 522.3,865.14 561,903.84 613.84,903.84 v1(614,904)
  Bottom Layer w9: v1(415,1291) 415,1261 554,1122 554,1109.38 631,1032.38 631,934.72 614,917.72 v1(614,904)
MSPACLK: R17.2 | length 88.4
  Top Layer w10: R17.2@313,267.5 313,230 v6(349,194)
NetC4_1: C4.1 U2.4 | length 85.4
  Top Layer w20: U2.4@61.6,1206.76 61.6,1133.91 C4.1@70.5,1125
